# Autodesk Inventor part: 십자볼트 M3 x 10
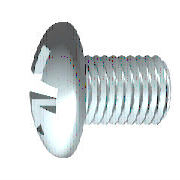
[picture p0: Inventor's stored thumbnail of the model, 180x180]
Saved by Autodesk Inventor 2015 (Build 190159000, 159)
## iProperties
IsCustomPart: 0
Created: 2012-02
Part Number: 십자볼트 M3 x 10
Material: 스테인리스강
Description: 십자 오목 머리 나사
Document SubType Name: Modeling
Standard: KS B 1023
Designer: mduedu
Standards Organization: KS
Language: ko-KR
Size Designation: A  M 3 x 10 - H
Categories: <MemberInstance><Categories><Category DisplayName="조임쇠" InternalName="e4da775c-781d-43d5-af7c-5136215cf5a6" Mnemonic="FSTN"><Category DisplayName="볼트" InternalN
Density: 1 g/cm^3
Appearance: 반광택
Author: mduedu
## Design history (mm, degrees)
body "Solid1"
workplane "Work Plane3"
sketch "스케치2"
  geometry: L1 (-3.72, 0)-(3.72, 0) reference; L2 (0, -3.72)-(0, 3.72) reference; L3 (0, 1.5)-(0, 0); L4 (0, 0)-(1.5, 0); L5 (0, 0)-(1.879, 1.879); L6 (0.253, 1.479)-(0.261, 0.456); L7 (1.479, 0.253)-(0.456, 0.261); L8 (0.253, -1.479)-(0.261, -0.456); L9 (1.479, -0.253)-(0.456, -0.261); L10 (-0.253, 1.479)-(-0.261, 0.456); L11 (-1.479, 0.253)-(-0.456, 0.261); L12 (-1.479, -0.253)-(-0.456, -0.261); L13 (-0.253, -1.479)-(-0.261, -0.456); A1 r 0.45 centre (0, 0) between (0.45, 0) and (0, 0.45); A2 r 1.5 centre (0, 0) between (1.5, 0) and (1.479, 0.253); A3 r 1.5 centre (0, 0) between (0.253, 1.479) and (0, 1.5); A4 r 1.5 centre (0, 0) between (1.479, 0.253) and (0.253, 1.479); A5 r 1.5 centre (0, 0) between (0, -1.5) and (0.253, -1.479); A6 r 1.5 centre (0, 0) between (0.253, -1.479) and (1.479, -0.253); A7 r 1.5 centre (0, 0) between (1.479, -0.253) and (1.5, 0); A8 r 1.5 centre (0, 0) between (-1.479, 0.253) and (-1.5, 0); A9 r 1.5 centre (0, 0) between (-0.253, 1.479) and (-1.479, 0.253); A10 r 1.5 centre (0, 0) between (0, 1.5) and (-0.253, 1.479); A11 r 1.5 centre (0, 0) between (-1.5, 0) and (-1.479, -0.253); A12 r 1.5 centre (0, 0) between (-1.479, -0.253) and (-0.253, -1.479); A13 r 1.5 centre (0, 0) between (-0.253, -1.479) and (0, -1.5); A14 r 0.525 centre (0, 0) between (0.525, 0) and (0, 0.525); A15 r 0.197 centre (0.457, 0.457) between (0.261, 0.456) and (0.456, 0.261); A16 r 0.197 centre (0.457, -0.457) between (0.456, -0.261) and (0.261, -0.456); A17 r 0.197 centre (-0.457, 0.457) between (-0.456, 0.261) and (-0.261, 0.456); A18 r 0.197 centre (-0.457, -0.457) between (-0.261, -0.456) and (-0.456, -0.261); 1 further point
  constraints: 38 point on circle, 22 end point, 19 symmetric about line, 18 centre point, 4 coincident, 3 collinear, 3 point on line, 3 tangent, 1 perpendicular, 21 other
  dimensions: "d4" = 45 deg angle of L5 L4; "d5" = 0.9 diameter of A1 (= 0.3 x SDM); "d6" = 3 diameter of A4 (= SDM); "d7" = 0.2525 distance from line of L6.start L3 (= 0.5 x SBR); "d14" = 1.05 diameter of A14 (= 0.35 x SDM)
extrude "슬롯" join sketch "스케치2" taper "d15" = 5 deg; stored distance "d54" = 10
revolve "절단부" stored, may be unused: angle "d56" = 90 deg
revolve "본체" stored, may be unused: angle "d18" = 90 deg
workplane "Work Plane1"
sketch "스케치1"
  geometry: L1 (10, 0)-(10, 1.5); L2 (10, 1.5)-(1, 1.5); L3 (3.962, 5.08)-(3.962, 5.08); L4 (-2.4, 0)-(-2.4, 2.59); L5 (-2.2, 1.4)-(-1.036, 0.82); L6 (-1.036, 0.82)-(-0.6, 0); L7 (-0.6, 0)-(10, 0); L8 (-5.105, 0)-(12.517, 0) reference; L9 (0, -1.016)-(0, 6.096) reference; L10 (-2.2, 1.4)-(-2.4, 1.5); L11 (-1.636, 2.657)-(-2.4, 2.59); L12 (-1.636, 2.657)-(0, 2.8); L13 (0, 2.8)-(0, 1.347); L14 (0, 1.347)-(0.693, 1.347); L15 (0.693, 1.347)-(1, 1.5); L16 (1, 1.5)-(0, 1.5); A1 r 5 centre (2.6, 0) between (-1.636, 2.657) and (-2.4, 0)
  constraints: 28 end point, 5 point on line, 4 collinear, 4 point on circle, 3 parallel, 2 perpendicular, 1 centre point, 1 horizontal, 1 tangent
  dimensions: "d1" = 3 diameter of L2 L7 (= GD); "d2" = 1.8 distance from line of L6.end L4 (= STI); "d11" = 3 diameter of L10.end L7 (= SDM); "d12" = 62 deg angle of L6 L7; "d13" = 26.5 deg angle of L5 L7; "d17" = 5.6 diameter of L12.end L7 (= KOD); "d19" = 5 deg angle of L12 L7 (= KEWI); "d20" = 2.4 distance between parallel lines of L4 L13 (= KOH); "d21" = 5 radius of A1 (= KR); "d23" = 2.6935 diameter of L14 L7 (= BDM); "d24" = 9 distance of L1.end L2.end (= GEL); "d25" = 0.30673 horizontal distance of L14.end L2.end (= GAL); "d28" = 10 distance between parallel lines of L1 L13 (= NLG)
fillet "모깎기1" dims "d29" = 1.2 (= RR)
fillet "모깎기2" dims "d16" = 0.101 (= 0.2 x SBR)
feature "스레드" dims "d8" = 9 (= GEL), "d9" = 0
chamfer "모따기1" distance "d26" = 0.30673 (= -0.5 x SPD + 0.5 x GD); stored, may be unused: second distance "d27" = 0.30683 (computed from GUL), angle "d78" = 45 deg
other parameters: "GD" = 3 (= NND) [user parameter; used in 2 equation terms], "NLG" = 10 [user parameter; used in 1 equation term], "GEL" = 9 [user parameter; used in 2 equation terms], "KOD" = 5.6 [user parameter; used in 1 equation term], "KOH" = 2.4 [user parameter; used in 2 equation terms], "SDM" = 3 [user parameter; used in 4 equation terms], "STI" = 1.8 [user parameter; used in 1 equation term], "SBR" = 0.505 [user parameter; used in 2 equation terms], "GAL" = 0.30673 (= 0.61345 x PTC) [user parameter; used in 1 equation term], "SPD" = 2.38655 (= NND - 1.2269 x PTC) [user parameter; used in 1 equation term], "KEWI" = 5 deg [user parameter; used in 1 equation term], "d3" = -2.4 (= -KOH), "d10" = 0, "KR" = 5 [user parameter; used in 1 equation term], "BDM" = 2.6935 [user parameter; used in 1 equation term], "GUL" = 0.30673 (= 0.61345 x PTC) [user parameter; used in 1 equation term], "RR" = 1.2 [user parameter; used in 1 equation term], "d79" = 0, "d80" = 0, "PTC" = 0.5 [user parameter; used in 5 equation terms], "THREADDIA" = 3 [user parameter; used in 1 equation term], "TOA" = 30 deg [user parameter], "NND" = 3 [user parameter; used in 2 equation terms], "GD1" = 2.38655 (= THREADDIA - 1.2269 x PTC) [user parameter]
